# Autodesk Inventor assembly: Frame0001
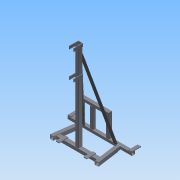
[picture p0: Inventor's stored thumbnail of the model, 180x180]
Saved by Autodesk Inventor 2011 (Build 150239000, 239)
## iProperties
Created: 2020-11
Part Number: Frame0001
Document SubType Name: Assembly
Designer: PC
_FrameDoc: Frame Assembly
_Version: 15.0.0
Author: PC
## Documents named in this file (48)
- C:\Users\PC\Documents\Inventor\workshop-crane-powered-by-drill\1_marco-inferior\Frame\Frame0001.iam
- C:\Users\PC\Documents\Inventor\workshop-crane-powered-by-drill\1_marco-inferior\Frame\Skeleton0001.ipt
- C:\Users\PC\Documents\Inventor\workshop-crane-powered-by-drill\1_marco-inferior\Frame\DIN 50 x 50 x 4 00000001.ipt
- DIN 50 x 50 x 4 00000001.ipt
- C:\Users\PC\Documents\Inventor\workshop-crane-powered-by-drill\1_marco-inferior\Frame\DIN 50 x 50 x 4 00000002.ipt
- DIN 50 x 50 x 4 00000002.ipt
- C:\Users\PC\Documents\Inventor\workshop-crane-powered-by-drill\1_marco-inferior\Frame\DIN 50 x 50 x 4 00000003.ipt
- DIN 50 x 50 x 4 00000003.ipt
- C:\Users\PC\Documents\Inventor\workshop-crane-powered-by-drill\1_marco-inferior\Frame\DIN 60 x 60 x 4 00000004.ipt
- DIN 60 x 60 x 4 00000004.ipt
- C:\Users\PC\Documents\Inventor\workshop-crane-powered-by-drill\1_marco-inferior\Frame\DIN 50 x 50 x 4 00000005.ipt
- DIN 50 x 50 x 4 00000005.ipt
- C:\Users\PC\Documents\Inventor\workshop-crane-powered-by-drill\1_marco-inferior\Frame\DIN 50 x 50 x 4 00000006.ipt
- DIN 50 x 50 x 4 00000006.ipt
- C:\Users\PC\Documents\Inventor\workshop-crane-powered-by-drill\1_marco-inferior\Frame\DIN 50 x 50 x 4 00000007.ipt
- DIN 50 x 50 x 4 00000007.ipt
- C:\Users\PC\Documents\Inventor\workshop-crane-powered-by-drill\1_marco-inferior\Frame\DIN 50 x 50 x 4 00000008.ipt
- DIN 50 x 50 x 4 00000008.ipt
- C:\Users\PC\Documents\Inventor\workshop-crane-powered-by-drill\1_marco-inferior\Frame\DIN 60 x 60 x 4 00000009.ipt
- DIN 60 x 60 x 4 00000009.ipt
- C:\Users\PC\Documents\Inventor\workshop-crane-powered-by-drill\1_marco-inferior\Frame\DIN 45 x 8 00000010.ipt
- DIN 45 x 8 00000010.ipt
- C:\Users\PC\Documents\Inventor\workshop-crane-powered-by-drill\1_marco-inferior\Frame\DIN 45 x 8 00000011.ipt
- DIN 45 x 8 00000011.ipt
- C:\Users\PC\Documents\Inventor\workshop-crane-powered-by-drill\1_marco-inferior\Frame\DIN 45 x 8 00000012.ipt
- DIN 45 x 8 00000012.ipt
- C:\Users\PC\Documents\Inventor\workshop-crane-powered-by-drill\1_marco-inferior\Frame\DIN 45 x 8 00000013.ipt
- DIN 45 x 8 00000013.ipt
- C:\Users\PC\Documents\Inventor\workshop-crane-powered-by-drill\1_marco-inferior\Frame\DIN 60 x 60 x 4 00000014.ipt
- DIN 60 x 60 x 4 00000014.ipt
- C:\Users\PC\Documents\Inventor\workshop-crane-powered-by-drill\1_marco-inferior\Frame\DIN 60 x 60 x 4 00000020.ipt
- DIN 60 x 60 x 4 00000020.ipt
- C:\Users\PC\Documents\Inventor\workshop-crane-powered-by-drill\1_marco-inferior\Frame\DIN 50 x 12 00000031.ipt
- DIN 50 x 12 00000031.ipt
- C:\Users\PC\Documents\Inventor\workshop-crane-powered-by-drill\1_marco-inferior\Frame\DIN 50 x 12 00000032.ipt
- DIN 50 x 12 00000032.ipt
- C:\Users\PC\Documents\Inventor\workshop-crane-powered-by-drill\1_marco-inferior\Frame\DIN 50 x 12 00000033.ipt
- DIN 50 x 12 00000033.ipt
- C:\Users\PC\Documents\Inventor\workshop-crane-powered-by-drill\1_marco-inferior\Frame\DIN 50 x 12 00000034.ipt
- DIN 50 x 12 00000034.ipt
- C:\Users\PC\Documents\Inventor\workshop-crane-powered-by-drill\1_marco-inferior\Frame\DIN 25 x 5 00000039.ipt
- DIN 25 x 5 00000039.ipt
- C:\Users\PC\Documents\Inventor\workshop-crane-powered-by-drill\1_marco-inferior\Frame\DIN 25 x 5 00000040.ipt
- DIN 25 x 5 00000040.ipt
- C:\Users\PC\Documents\Inventor\workshop-crane-powered-by-drill\1_marco-inferior\Frame\DIN 45 x 8 00000041.ipt
- DIN 45 x 8 00000041.ipt
- C:\Users\PC\Documents\Inventor\workshop-crane-powered-by-drill\1_marco-inferior\Frame\DIN 45 x 8 00000042.ipt
- DIN 45 x 8 00000042.ipt
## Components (24 placed, 24 different names)
1. Frame Reference Model
2. DIN 50 x 50 x 4 00000001:1
3. DIN 50 x 50 x 4 00000002:1
4. DIN 50 x 50 x 4 00000003:1
5. DIN 60 x 60 x 4 00000004:1
6. DIN 50 x 50 x 4 00000005:1
7. DIN 50 x 50 x 4 00000006:1
8. DIN 50 x 50 x 4 00000007:1
9. DIN 50 x 50 x 4 00000008:1
10. DIN 60 x 60 x 4 00000009:1
11. DIN 45 x 8 00000010:1
12. DIN 45 x 8 00000011:1
13. DIN 45 x 8 00000012:1
14. DIN 45 x 8 00000013:1
15. DIN 60 x 60 x 4 00000014:1
16. DIN 60 x 60 x 4 00000020:1
17. DIN 50 x 12 00000031:1
18. DIN 50 x 12 00000032:1
19. DIN 50 x 12 00000033:1
20. DIN 50 x 12 00000034:1
21. DIN 25 x 5 00000039:1
22. DIN 25 x 5 00000040:1
23. DIN 45 x 8 00000041:1
24. DIN 45 x 8 00000042:1
